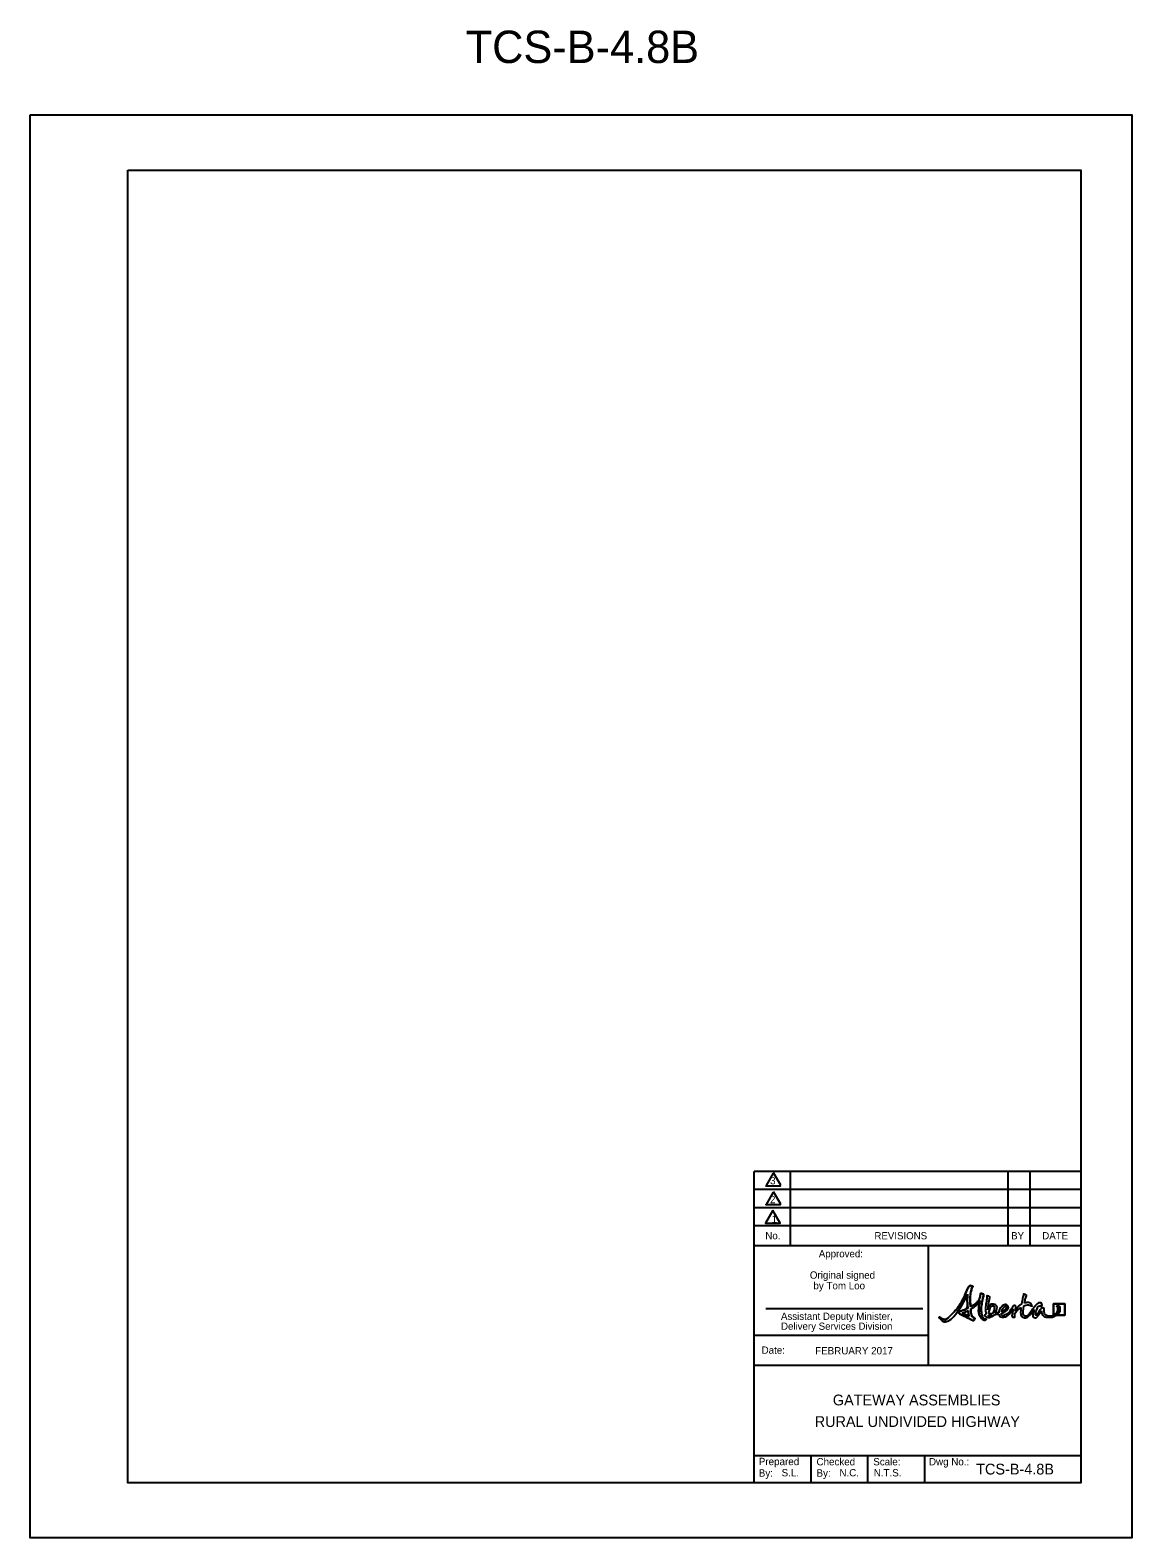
# Model space of a CAD drawing. Extents: x 1535 to 2422, y 125 to 421.
# Drawn here: x 1939.6 to 2155.6, y 125 to 420.6 of the extents above; entities that cross this region are included whole.
import ezdxf

# ---------------------------------------------------------------- set-up
doc = ezdxf.new("R2010")
doc.units = 0
for name, color, linetype in [('Level 1', 7, 'Continuous'), ('Level 10', 7, 'Continuous'), ('Level 2', 7, 'Continuous'), ('Level 22', 7, 'Continuous'), ('Level 44', 7, 'Continuous'), ('Level 53', 7, 'Continuous'), ('Level 60', 7, 'Continuous')]:
    doc.layers.add(name, color=color, linetype=linetype)

msp = doc.modelspace()

# ---------------------------------------------------------------- linework, layer by layer
at = {"layer": 'Level 1'}
for p, q in [((2145.4, 196.82), (2081.52, 196.82)), ((2145.4, 193.27), (2081.52, 193.27)), ((2145.4, 189.72), (2081.52, 189.72)), ((2145.4, 186.18), (2081.52, 186.18)), ((2081.53, 135.79), (2081.53, 182.27)), ((2081.53, 182.27), (2145.4, 182.27)), ((2115.59, 182.27), (2115.59, 158.85)), ((2081.53, 164.71), (2115.59, 164.71)), ((2081.53, 158.85), (2145.4, 158.85)), ((2081.53, 141.11), (2145.4, 141.11)), ((2092.66, 135.79), (2092.66, 141.11)), ((2103.8, 135.79), (2103.8, 141.11)), ((2114.93, 141.11), (2114.93, 135.79))]:
    msp.add_line(p, q, dxfattribs=at)
msp.add_lwpolyline([(2085.15, 189.16), (2083.73, 186.69), (2086.57, 186.69)], close=True, dxfattribs=at)
at = {"layer": 'Level 2'}
msp.add_line((2115.59, 182.27), (2115.59, 182.27), dxfattribs=at)
at = {"layer": 'Level 22'}
msp.add_line((2097.01, 135.79), (2097.01, 135.79), dxfattribs=at)
at = {"layer": 'Level 53'}
msp.add_line((2140.78, 168.64), (2140.23, 168.64), dxfattribs=at)
msp.add_lwpolyline([(2140.78, 168.64), (2142.4, 168.64), (2142.4, 170.87), (2140.17, 170.87), (2140.17, 168.64), (2140.23, 168.64)], dxfattribs=at)
for points, degree in [([(2126.8, 167.83), (2126.56, 167.87), (2126.24, 168.19), (2126.15, 168.73), (2125.98, 169.7), (2126.08, 170.65), (2126.36, 172.07), (2126.42, 172.34), (2126.6, 172.8), (2126.02, 172.89), (2125.83, 172.92), (2125.93, 172.83), (2125.87, 172.59), (2125.65, 171.53), (2124.78, 170.76), (2123.92, 170.25), (2123.82, 171.46), (2123.86, 172.81), (2124.09, 173.64), (2124.28, 174.33), (2124.51, 174.2), (2124.23, 174.35), (2123.93, 174.5), (2123.61, 174.3), (2123.35, 173.78), (2123.09, 173.26), (2121.89, 170.45), (2119.98, 168.55), (2119, 167.57), (2118.12, 168.08), (2117.94, 168.22), (2117.8, 168.35), (2117.74, 168.16), (2117.92, 167.97), (2118.71, 167.11), (2119.87, 167.6), (2120.29, 168.02), (2121.45, 169.19), (2122.8, 171.69), (2123.35, 172.75), (2123.3, 172.15), (2123.28, 171.15), (2123.39, 169.97), (2122.8, 169.69), (2122.27, 169.52), (2122.02, 169.45), (2121.75, 169.38), (2121.58, 169.27), (2121.58, 169.14), (2121.57, 169.01), (2121.75, 168.89), (2122.02, 168.77), (2122.49, 168.54), (2123.86, 167.89), (2124.2, 167.7), (2124.49, 167.53), (2124.63, 167.66), (2124.71, 167.84), (2124.82, 168.08), (2124.52, 168.22), (2124.22, 168.3), (2124.11, 168.7), (2124.01, 169.24), (2123.95, 169.83), (2124.65, 170.26), (2125.34, 170.83), (2125.73, 171.54), (2125.63, 170.95), (2125.38, 168.92), (2126.02, 168.06), (2126.16, 167.87), (2126.47, 167.66), (2126.78, 167.69), (2126.92, 167.71), (2126.99, 167.8), (2126.98, 167.83), (2126.96, 167.86), (2126.88, 167.82), (2126.8, 167.83)], 3), ([(2123.92, 170.25), (2123.82, 171.46), (2123.86, 172.81), (2124.09, 173.64), (2124.28, 174.33), (2124.51, 174.2), (2124.23, 174.35), (2123.93, 174.5), (2123.61, 174.3), (2123.35, 173.78), (2123.09, 173.26), (2121.89, 170.45), (2119.98, 168.55), (2119, 167.57), (2118.12, 168.08), (2117.94, 168.22), (2117.8, 168.35), (2117.74, 168.16), (2117.92, 167.97), (2118.71, 167.11), (2119.87, 167.6), (2120.29, 168.02), (2121.45, 169.19), (2122.8, 171.69), (2123.35, 172.75)], 3), ([(2123.35, 172.75), (2123.3, 172.15), (2123.28, 171.15), (2123.39, 169.97)], 2), ([(2126.8, 167.83), (2126.56, 167.87), (2126.24, 168.19), (2126.15, 168.73), (2125.98, 169.7), (2126.08, 170.65), (2126.36, 172.07), (2126.42, 172.34), (2126.6, 172.8), (2126.02, 172.89), (2125.83, 172.92), (2125.93, 172.83), (2125.87, 172.59), (2125.65, 171.53), (2124.78, 170.76), (2123.92, 170.25)], 3), ([(2123.95, 169.83), (2124.65, 170.26), (2125.34, 170.83), (2125.73, 171.54)], 2), ([(2125.73, 171.54), (2125.63, 170.95), (2125.38, 168.92), (2126.02, 168.06), (2126.16, 167.87), (2126.47, 167.66), (2126.78, 167.69), (2126.92, 167.71), (2126.99, 167.8), (2126.98, 167.83), (2126.96, 167.86), (2126.88, 167.82), (2126.8, 167.83)], 3), ([(2127.33, 169.67), (2127.38, 170.24), (2127.47, 170.93), (2127.6, 171.58), (2127.65, 171.84), (2127.84, 172.31), (2127.25, 172.4), (2127.07, 172.43), (2127.1, 172.34), (2127.11, 172.09), (2127.13, 171.75), (2126.76, 169.71), (2126.95, 168.82)], 3), ([(2134.49, 171.01), (2134.55, 171.31), (2134.63, 171.61), (2134.71, 171.91), (2134.79, 172.17), (2135.01, 172.64), (2134.43, 172.73), (2134.25, 172.76), (2134.32, 172.67), (2134.26, 172.42), (2134.15, 171.96), (2134.01, 171.37), (2133.91, 170.78)], 3), ([(2123.39, 169.97), (2122.8, 169.69), (2122.27, 169.52), (2122.02, 169.45), (2121.75, 169.38), (2121.58, 169.27), (2121.58, 169.14), (2121.57, 169.01), (2121.75, 168.89), (2122.02, 168.77), (2122.49, 168.54), (2123.86, 167.89), (2124.2, 167.7), (2124.49, 167.53), (2124.63, 167.66), (2124.71, 167.84), (2124.82, 168.08), (2124.52, 168.22), (2124.22, 168.3)], 3), ([(2122.32, 169.04), (2122.63, 169.15), (2123.03, 169.32), (2123.44, 169.54)], 2), ([(2122.32, 169.04), (2122.63, 169.15), (2123.03, 169.32), (2123.44, 169.54), (2123.5, 169.06), (2123.56, 168.72), (2123.62, 168.47), (2123.32, 168.58), (2122.89, 168.75), (2122.32, 169.04)], 3), ([(2123.62, 168.47), (2123.32, 168.58), (2122.89, 168.75), (2122.32, 169.04)], 2), ([(2123.44, 169.54), (2123.5, 169.06), (2123.56, 168.72), (2123.62, 168.47)], 2), ([(2124.22, 168.3), (2124.11, 168.7), (2124.01, 169.24), (2123.95, 169.83)], 2), ([(2126.95, 168.82), (2126.7, 168.74), (2126.6, 168.55), (2126.92, 168.35), (2127.15, 168.21), (2127.64, 168.17), (2128.13, 168.41), (2128.31, 168.5), (2128.46, 168.62), (2128.59, 168.77)], 3), ([(2128.77, 169.01), (2129.19, 169.68), (2129.15, 170.59), (2128.54, 170.75), (2127.84, 170.92), (2127.48, 170.24), (2127.33, 169.67)], 3), ([(2127.41, 168.45), (2127.44, 168.48), (2127.46, 168.52), (2127.46, 168.56), (2127.46, 168.59), (2127.46, 168.63), (2127.46, 168.66)], 3), ([(2127.46, 168.66), (2127.59, 168.66), (2127.79, 168.68), (2128.02, 168.7)], 2), ([(2127.48, 168.88), (2127.58, 169.6), (2127.95, 170.59), (2128.41, 170.43), (2128.68, 170.34), (2128.54, 169.5), (2128.2, 168.94)], 3), ([(2128.2, 168.94), (2127.97, 168.92), (2127.74, 168.9), (2127.48, 168.88)], 2), ([(2128.02, 168.7), (2127.9, 168.57), (2127.76, 168.47), (2127.61, 168.45)], 2), ([(2128.59, 168.77), (2128.89, 168.8), (2129.2, 168.85), (2129.48, 168.91)], 2), ([(2129.47, 169.13), (2129.27, 169.08), (2129.03, 169.05), (2128.77, 169.01)], 2), ([(2130, 169.03), (2130.09, 169.06), (2130.18, 169.09), (2130.25, 169.13), (2131.14, 169.52), (2131.44, 170.11), (2131.21, 170.47), (2131, 170.81), (2130.39, 170.7), (2129.91, 170.2), (2129.67, 169.95), (2129.49, 169.52), (2129.47, 169.13)], 3), ([(2129.48, 168.91), (2129.53, 168.51), (2129.78, 168.21), (2130.38, 168.27), (2131.22, 168.35), (2131.98, 169.39), (2132.26, 169.89)], 3), ([(2132.67, 169.45), (2132.73, 169.72), (2132.81, 170.03), (2132.82, 170.24), (2132.83, 170.45), (2132.68, 170.5), (2132.62, 170.52), (2132.49, 170.55), (2132.34, 170.49), (2132.19, 170.28), (2131.84, 169.78), (2131.39, 168.99), (2130.71, 168.66), (2130.22, 168.43), (2130.01, 168.67), (2130, 169.03)], 3), ([(2130.47, 170.15), (2130.77, 170.43), (2130.91, 170.41), (2130.95, 170.33), (2131.04, 170.17), (2130.69, 169.61), (2130.02, 169.3)], 3), ([(2130.02, 169.3), (2130.08, 169.61), (2130.24, 169.94), (2130.47, 170.15)], 2), ([(2132.26, 169.89), (2132.21, 169.35), (2131.86, 168.18), (2132.45, 168.24), (2132.69, 168.26), (2132.59, 168.3), (2132.6, 168.5), (2132.65, 169.21), (2133.24, 169.81), (2133.82, 170.17)], 3), ([(2133.91, 170.78), (2133.44, 170.5), (2132.99, 170.05), (2132.67, 169.45)], 2), ([(2133.82, 170.17), (2133.72, 169.31), (2133.76, 168.54), (2134.15, 168.29), (2134.87, 167.84), (2135.89, 169.03), (2136.46, 169.75)], 3), ([(2139.54, 168.44), (2138.63, 168.44), (2138.39, 169.15), (2138.35, 169.51), (2138.32, 169.74), (2138.37, 170.08), (2137.96, 170.03), (2137.68, 170), (2137.42, 169.45), (2137.07, 168.99), (2136.76, 168.59), (2136.62, 168.63), (2136.69, 168.97), (2136.78, 169.4), (2137.14, 170.4), (2137.55, 170.47), (2137.74, 170.51), (2137.8, 170.18), (2137.89, 170.38), (2137.98, 170.59), (2137.9, 171.04), (2137.47, 171.04), (2137.18, 171.04), (2136.82, 170.73), (2136.53, 170.37), (2136.28, 170.06), (2134.99, 168.17), (2134.45, 168.57), (2134.2, 168.77), (2134.22, 169.54), (2134.38, 170.46)], 3), ([(2134.38, 170.46), (2135.02, 170.71), (2135.55, 170.62), (2135.85, 170.48), (2136, 170.41), (2136.02, 170.42), (2135.96, 170.58), (2135.86, 170.82), (2135.35, 171.2), (2134.55, 171.03), (2134.53, 171.02), (2134.51, 171.02), (2134.49, 171.01)], 3), ([(2136.46, 169.75), (2136.17, 169.11), (2136.01, 168.28), (2136.44, 168.16), (2136.94, 168.01), (2137.34, 168.85), (2137.81, 169.49)], 3), ([(2137.81, 169.49), (2137.86, 169.03), (2138.17, 168.23), (2139.4, 168.23), (2139.96, 168.23), (2140.43, 168.39), (2140.78, 168.64)], 3), ([(2140.23, 168.64), (2140.03, 168.52), (2139.79, 168.44), (2139.54, 168.44)], 2), ([(2140.17, 170.87), (2140.17, 170.87), (2140.17, 168.64), (2140.17, 168.64), (2140.17, 168.64), (2140.23, 168.64), (2140.23, 168.64), (2140.72, 168.93), (2141.04, 169.48), (2141.04, 169.94), (2141.04, 170.33), (2140.83, 170.31), (2140.86, 170.37), (2140.92, 170.53), (2141.42, 170.44), (2141.44, 169.88), (2141.47, 169.41), (2141.22, 168.95), (2140.78, 168.64), (2140.78, 168.64), (2142.4, 168.64), (2142.4, 168.64), (2142.4, 168.64), (2142.4, 170.87), (2142.4, 170.87), (2142.4, 170.87), (2140.17, 170.87), (2140.17, 170.87)], 3), ([(2140.23, 168.64), (2140.72, 168.93), (2141.04, 169.48), (2141.04, 169.94), (2141.04, 170.33), (2140.83, 170.31), (2140.86, 170.37), (2140.92, 170.53), (2141.42, 170.44), (2141.44, 169.88), (2141.47, 169.41), (2141.22, 168.95), (2140.78, 168.64)], 3), ([(2127.61, 168.45), (2127.53, 168.44), (2127.46, 168.44), (2127.41, 168.45)], 2)]:
    msp.add_open_spline(points, degree=degree, dxfattribs=at)
at = {"layer": 'Level 60'}
for p, q in [((1939.55, 403.98), (1939.55, 403.98)), ((2081.53, 190.35), (2081.53, 196.82)), ((2088.62, 190.35), (2088.62, 196.82)), ((2131.21, 196.82), (2131.21, 182.27)), ((2135.52, 196.82), (2135.52, 182.27)), ((2081.53, 182.27), (2081.53, 190.35)), ((2088.62, 182.27), (2088.62, 190.35)), ((2083.79, 169.95), (2114.6, 169.95)), ((2155.55, 124.98), (2155.55, 124.98))]:
    msp.add_line(p, q, dxfattribs=at)
for points in [[(1939.55, 403.98), (2155.55, 403.98), (2155.55, 124.98), (1939.55, 124.98)], [(1958.68, 393.17), (2145.55, 393.17), (2145.55, 135.79), (1958.68, 135.79)]]:
    msp.add_lwpolyline(points, close=True, dxfattribs=at)
for points in [[(2085.23, 196.49), (2083.83, 194.07)], [(2086.71, 194.14), (2085.31, 196.57)], [(2083.83, 194.07), (2083.81, 194.02), (2086.65, 194.02), (2086.62, 194.07)], [(2085.23, 192.78), (2083.83, 190.35)], [(2086.71, 190.43), (2085.31, 192.85)], [(2083.83, 190.35), (2083.81, 190.31), (2086.65, 190.31), (2086.62, 190.35)]]:
    msp.add_lwpolyline(points, dxfattribs=at)

# ---------------------------------------------------------------- texts
at = {"layer": 'Level 1'}
for s, height, p in [('3', 1.45, (2084.62, 194.29)), ('2', 1.45, (2084.6, 190.58)), ('1', 1.45, (2084.92, 186.75)), ('No.', 1.419, (2083.7, 183.51)), ('REVISIONS', 1.419, (2105.08, 183.51)), ('BY', 1.419, (2131.89, 183.51)), ('DATE', 1.419, (2137.99, 183.51)), ('Date:', 1.434, (2082.96, 161.07)), ('Prepared', 1.441, (2082.41, 139.23)), ('Checked', 1.434, (2093.73, 139.19)), ('Scale:', 1.434, (2104.86, 139.19)), ('Dwg No.:', 1.434, (2115.78, 139.19)), ('By:', 1.441, (2082.41, 136.97)), ('By:', 1.441, (2093.73, 136.97)), ('    N.T.S.   ', 1.4336, (2102.83, 137.02))]:
    msp.add_text(s, height=height, rotation=360, dxfattribs=at).set_placement(p)
at = {"layer": 'Level 10'}
for s, p in [('GATEWAY ASSEMBLIES', (2096.93, 150.95)), ('RURAL UNDIVIDED HIGHWAY', (2093.37, 146.72))]:
    msp.add_text(s, height=2.116, rotation=360, dxfattribs=at).set_placement(p)
at = {"layer": 'Level 44'}
msp.add_text('TCS-B-4.8B', height=6.348, rotation=360, dxfattribs=at).set_placement((2024.95, 414.16))
at = {"layer": 'Level 60'}
for s, height, p in [('Approved:', 1.419, (2094.18, 179.98)), ('Original signed', 1.434, (2092.42, 175.79)), ('by Tom Loo', 1.434, (2093.12, 173.71)), ('Assistant Deputy Minister,', 1.4194, (2086.76, 167.72)), ('Delivery Services Division', 1.4194, (2086.77, 165.77)), ('FEBRUARY 2017', 1.434, (2093.47, 160.95)), ('TCS-B-4.8B', 2.116, (2125.03, 137.4))]:
    msp.add_text(s, height=height, dxfattribs=at).set_placement(p)
for s, p in [('S.L.', (2086.89, 137.03)), ('N.C.', (2098.22, 137.03))]:
    msp.add_text(s, height=1.434, rotation=360, dxfattribs=at).set_placement(p)

doc.saveas('drawing.dxf')
